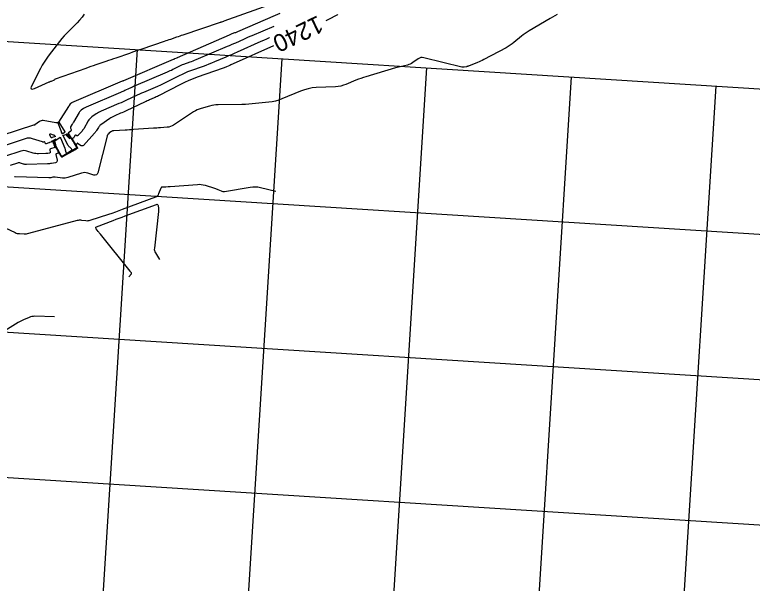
# Model space of a CAD drawing. Extents: x 658976 to 668721, y 639543 to 647196.
# Drawn here: x 662592.9 to 662847.1, y 641855.6 to 642051.6 of the extents above; entities that cross this region are included whole.
import ezdxf

# ---------------------------------------------------------------- set-up
doc = ezdxf.new("R2010")
doc.units = 0
for name, color, linetype in [('Ex_Contour Labels', 7, 'Continuous'), ('Ex_Major Contours', 7, 'Continuous'), ('Ex_Minor Contours', 7, 'Continuous'), ('R_Grid', 7, 'Continuous')]:
    doc.layers.add(name, color=color, linetype=linetype)

msp = doc.modelspace()

# ---------------------------------------------------------------- linework, layer by layer
at = {"layer": 'Ex_Major Contours'}
for points in [[(662704.31, 642051.66), (662704.09, 642051.55), (662703.87, 642051.43), (662703.01, 642050.95), (662702.79, 642050.83), (662702.58, 642050.71), (662702.36, 642050.6), (662702.14, 642050.49), (662700.13, 642049.48)], [(662682.09, 642040.84), (662668.19, 642034.6), (662667.91, 642034.48), (662667.62, 642034.35), (662667.33, 642034.23), (662667.05, 642034.1), (662665.9, 642033.61), (662665.61, 642033.49), (662665.32, 642033.38), (662665.03, 642033.27), (662664.73, 642033.16), (662655.79, 642029.99), (662654.32, 642029.44), (662652.87, 642028.85), (662651.44, 642028.2), (662650.03, 642027.51), (662642.4, 642023.58), (662642.03, 642023.39), (662641.65, 642023.21), (662641.27, 642023.04), (662640.88, 642022.87), (662639.34, 642022.21), (662638.95, 642022.04), (662638.57, 642021.87), (662638.19, 642021.7), (662637.81, 642021.52), (662631.27, 642018.43), (662630.79, 642018.21), (662630.31, 642018), (662629.83, 642017.78), (662629.35, 642017.57), (662627.42, 642016.75), (662626.95, 642016.53), (662626.48, 642016.29), (662626.03, 642016.03), (662625.6, 642015.74), (662622.49, 642013.56), (662622.25, 642013.38), (662622.04, 642013.17), (662621.85, 642012.95), (662621.69, 642012.7), (662621.08, 642011.66), (662620.92, 642011.4), (662620.75, 642011.15), (662620.57, 642010.92), (662620.37, 642010.69), (662616.58, 642006.53), (662616.39, 642006.38), (662616.2, 642006.31), (662615.99, 642006.32), (662615.76, 642006.42), (662614.5, 642007.22), (662614.45, 642007.24), (662614.41, 642007.24), (662614.38, 642007.22), (662614.34, 642007.18), (662614.2, 642006.93), (662614.18, 642006.91), (662614.16, 642006.88), (662614.14, 642006.86), (662614.12, 642006.84), (662614.01, 642006.75), (662614, 642006.74), (662613.98, 642006.73), (662613.97, 642006.73), (662613.96, 642006.72), (662613.91, 642006.7), (662613.9, 642006.69), (662613.89, 642006.69), (662613.89, 642006.68), (662613.9, 642006.67), (662614.49, 642005.69), (662614.53, 642005.6), (662614.53, 642005.52), (662614.49, 642005.46), (662614.42, 642005.4), (662614.05, 642005.18), (662613.96, 642005.13), (662613.87, 642005.07), (662613.77, 642005.02), (662613.68, 642004.97), (662609.29, 642002.53), (662609.18, 642002.48), (662609.08, 642002.49), (662609, 642002.54), (662608.93, 642002.63), (662608.68, 642003.09), (662608.61, 642003.21), (662608.55, 642003.32), (662608.48, 642003.43), (662608.4, 642003.54), (662607.78, 642004.46), (662607.75, 642004.51), (662607.74, 642004.52), (662607.74, 642004.5), (662607.75, 642004.45), (662607.88, 642004.11), (662607.89, 642004.08), (662607.89, 642004.05), (662607.89, 642004.03), (662607.89, 642004), (662607.86, 642003.88), (662607.85, 642003.85), (662607.83, 642003.83), (662607.81, 642003.82), (662607.79, 642003.8), (662607.23, 642003.64), (662607.14, 642003.6), (662607.08, 642003.54), (662607.06, 642003.46), (662607.06, 642003.36), (662607.44, 642001.38), (662607.45, 642001.07), (662607.36, 642000.83), (662607.17, 642000.66), (662606.88, 642000.56), (662605.5, 642000.29), (662605.16, 642000.23), (662604.81, 642000.18), (662604.46, 642000.15), (662604.11, 642000.14), (662596.88, 641999.95), (662596.62, 641999.95), (662596.36, 641999.98), (662596.1, 642000.03), (662595.85, 642000.1), (662594.84, 642000.42), (662594.59, 642000.47), (662594.34, 642000.49), (662594.09, 642000.47), (662593.83, 642000.41), (662591.26, 641999.57)]]:
    msp.add_lwpolyline(points, dxfattribs=at)
at = {"layer": 'Ex_Minor Contours'}
for points in [[(662616.81, 642051.7), (662616.06, 642050.69), (662615.24, 642049.72), (662614.38, 642048.79), (662610.82, 642045.17), (662609.94, 642044.25), (662609.1, 642043.31), (662608.28, 642042.33), (662607.5, 642041.34), (662604.41, 642037.29), (662603.66, 642036.26), (662602.96, 642035.21), (662602.31, 642034.12), (662601.71, 642033), (662598.72, 642027.13), (662598.44, 642026.41), (662598.5, 642026), (662598.9, 642025.92), (662599.64, 642026.16), (662604.74, 642028.39), (662604.93, 642028.47), (662605.11, 642028.55), (662605.3, 642028.63), (662605.48, 642028.71), (662606.52, 642029.16), (662606.56, 642029.18), (662606.59, 642029.2), (662606.62, 642029.22), (662606.64, 642029.25), (662606.74, 642029.36), (662606.77, 642029.38), (662606.79, 642029.4), (662606.83, 642029.42), (662606.86, 642029.44), (662617.46, 642033.17), (662618.33, 642033.47), (662619.19, 642033.77), (662620.06, 642034.07), (662620.92, 642034.37), (662624.39, 642035.55), (662625.26, 642035.84), (662626.12, 642036.14), (662626.99, 642036.44), (662627.85, 642036.74), (662632.49, 642038.36), (662633.55, 642038.73), (662634.61, 642039.1), (662635.67, 642039.46), (662636.74, 642039.83), (662644.48, 642042.44), (662645.02, 642042.63), (662645.55, 642042.81), (662646.09, 642042.99), (662646.62, 642043.18), (662648.76, 642043.92), (662649.3, 642044.11), (662649.84, 642044.29), (662650.37, 642044.47), (662650.91, 642044.65), (662663.82, 642048.99), (662663.94, 642049.02), (662664.05, 642049.06), (662664.17, 642049.1), (662664.29, 642049.14), (662664.95, 642049.37), (662664.96, 642049.38), (662664.98, 642049.38), (662664.99, 642049.39), (662665, 642049.39), (662665.06, 642049.42), (662665.07, 642049.42), (662665.08, 642049.43), (662665.1, 642049.43), (662665.11, 642049.44), (662682.24, 642055.52)], [(662684.22, 642051.97), (662682.6, 642051.24), (662669.63, 642045.65), (662669.4, 642045.55), (662669.16, 642045.45), (662668.92, 642045.36), (662668.68, 642045.27), (662667.7, 642044.92), (662667.46, 642044.84), (662667.22, 642044.74), (662666.98, 642044.65), (662666.75, 642044.54), (662648.88, 642036.7), (662648.86, 642036.69), (662648.85, 642036.68), (662648.83, 642036.68), (662648.82, 642036.67), (662648.75, 642036.65), (662648.74, 642036.64), (662648.72, 642036.64), (662648.71, 642036.63), (662648.69, 642036.63), (662647.96, 642036.3), (662647.83, 642036.24), (662647.71, 642036.18), (662647.58, 642036.13), (662647.45, 642036.07), (662630.38, 642028.81), (662630.35, 642028.79), (662630.31, 642028.77), (662630.27, 642028.76), (662630.24, 642028.74), (662630.09, 642028.67), (662630.05, 642028.65), (662630.01, 642028.64), (662629.98, 642028.62), (662629.94, 642028.6), (662612.43, 642021.13), (662612.39, 642021.11), (662612.34, 642021.09), (662612.3, 642021.07), (662612.26, 642021.04), (662612.1, 642020.93), (662612.07, 642020.9), (662612.03, 642020.87), (662612, 642020.83), (662611.98, 642020.79), (662611.68, 642020.29), (662611.62, 642020.19), (662611.57, 642020.1), (662611.51, 642020), (662611.44, 642019.9), (662608, 642014.58), (662608, 642014.57), (662607.99, 642014.56), (662608, 642014.55), (662608, 642014.55), (662608.01, 642014.52), (662608.02, 642014.51), (662608.02, 642014.5), (662608.02, 642014.5), (662608.03, 642014.49), (662610.14, 642011.17), (662610.15, 642011.15), (662610.15, 642011.12), (662610.14, 642011.1), (662610.13, 642011.08), (662610.03, 642010.99), (662610.01, 642010.97), (662609.99, 642010.95), (662609.96, 642010.93), (662609.94, 642010.9), (662609.41, 642010.45), (662609.41, 642010.44), (662609.41, 642010.44), (662609.4, 642010.45), (662609.4, 642010.45), (662609.39, 642010.48), (662609.38, 642010.48), (662609.03, 642011.11), (662608.98, 642011.22), (662608.93, 642011.33), (662608.88, 642011.44), (662608.84, 642011.55), (662607.88, 642014.22), (662607.85, 642014.28), (662607.8, 642014.33), (662607.74, 642014.35), (662607.67, 642014.36), (662607.35, 642014.33), (662607.27, 642014.33), (662607.2, 642014.33), (662607.12, 642014.34), (662607.04, 642014.35), (662602.63, 642015.04), (662602.3, 642015.06), (662601.98, 642015.01), (662601.68, 642014.91), (662601.39, 642014.74), (662599.77, 642013.55), (662599.74, 642013.53), (662599.72, 642013.52), (662599.69, 642013.51), (662599.66, 642013.51), (662599.51, 642013.49), (662599.5, 642013.49), (662599.48, 642013.49), (662599.47, 642013.49), (662599.46, 642013.5), (662599.41, 642013.51), (662599.39, 642013.52), (662599.38, 642013.52), (662599.37, 642013.51), (662599.36, 642013.51), (662582.63, 642008.05)], [(662779.93, 642051.64), (662779.12, 642051.17), (662778.31, 642050.7), (662777.5, 642050.23), (662770.24, 642046.01), (662769.54, 642045.58), (662768.85, 642045.12), (662768.18, 642044.64), (662767.53, 642044.13), (662764.98, 642042.02), (662764.33, 642041.51), (662763.66, 642041.04), (662762.97, 642040.6), (662762.25, 642040.19), (662754.58, 642036.1), (662754.03, 642035.82), (662753.48, 642035.55), (662752.93, 642035.3), (662752.36, 642035.07), (662749.32, 642033.85), (662749.13, 642033.79), (662748.95, 642033.73), (662748.76, 642033.68), (662748.57, 642033.64), (662747.8, 642033.51), (662747.61, 642033.48), (662747.42, 642033.48), (662747.22, 642033.5), (662747.03, 642033.53), (662733.86, 642036.73), (662733.34, 642036.8), (662732.85, 642036.77), (662732.38, 642036.62), (662731.93, 642036.36), (662730.15, 642035.08), (662729.71, 642034.79), (662729.25, 642034.55), (662728.77, 642034.36), (662728.26, 642034.22), (662726.2, 642033.75), (662725.69, 642033.63), (662725.18, 642033.5), (662724.67, 642033.36), (662724.16, 642033.22), (662713.96, 642030.19), (662713.07, 642029.91), (662712.2, 642029.61), (662711.33, 642029.29), (662710.47, 642028.95), (662707.04, 642027.53), (662706.18, 642027.22), (662705.29, 642026.98), (662704.39, 642026.82), (662703.48, 642026.74), (662696.84, 642026.44), (662695.44, 642026.32), (662694.06, 642026.07), (662692.71, 642025.71), (662691.39, 642025.22), (662684.94, 642022.54), (662683.86, 642022.13), (662682.75, 642021.8), (662681.63, 642021.56), (662680.48, 642021.39), (662675.85, 642020.9), (662674.69, 642020.79), (662673.53, 642020.71), (662672.37, 642020.65), (662671.21, 642020.62), (662662.97, 642020.49), (662662.23, 642020.46), (662661.5, 642020.38), (662660.77, 642020.25), (662660.05, 642020.07), (662657.19, 642019.28), (662656.48, 642019.06), (662655.8, 642018.78), (662655.15, 642018.45), (662654.52, 642018.07), (662647.6, 642013.5), (662647.1, 642013.21), (662646.56, 642012.99), (662646.01, 642012.84), (662645.43, 642012.76), (662643.07, 642012.59), (662642.47, 642012.54), (662641.88, 642012.5), (662641.29, 642012.46), (662640.7, 642012.42), (662633.82, 642011.95), (662633.1, 642011.9), (662632.38, 642011.86), (662631.65, 642011.82), (662630.93, 642011.78), (662626.98, 642011.57), (662626.79, 642011.55), (662626.61, 642011.5), (662626.43, 642011.43), (662626.27, 642011.33), (662625.34, 642010.68), (662625.33, 642010.67), (662625.32, 642010.66), (662625.31, 642010.65), (662625.31, 642010.64), (662625.28, 642010.59), (662625.27, 642010.58), (662625.26, 642010.57), (662625.25, 642010.56), (662625.25, 642010.55), (662624.96, 642010.24), (662624.93, 642010.2), (662624.9, 642010.16), (662624.87, 642010.11), (662624.85, 642010.06), (662624.78, 642009.87), (662624.76, 642009.82), (662624.74, 642009.77), (662624.73, 642009.72), (662624.71, 642009.67), (662621.48, 641997.04), (662621.29, 641996.59), (662621.01, 641996.32), (662620.63, 641996.22), (662620.15, 641996.3), (662618.03, 641996.97), (662617.5, 641997.09), (662616.97, 641997.13), (662616.44, 641997.09), (662615.91, 641996.96), (662611.17, 641995.43), (662610.71, 641995.31), (662610.24, 641995.24), (662609.76, 641995.22), (662609.28, 641995.26), (662606.76, 641995.61), (662606.57, 641995.62), (662606.39, 641995.62), (662606.21, 641995.6), (662606.03, 641995.56), (662605.3, 641995.37), (662605.12, 641995.32), (662604.94, 641995.3), (662604.75, 641995.28), (662604.57, 641995.28), (662593.02, 641995.69), (662592.89, 641995.7), (662592.76, 641995.72)], [(662682.19, 642047.54), (662674.57, 642044.3), (662673.86, 642044), (662673.15, 642043.7), (662672.45, 642043.38), (662671.74, 642043.07), (662668.93, 642041.81), (662668.23, 642041.5), (662667.52, 642041.19), (662666.82, 642040.88), (662666.11, 642040.58), (662655.26, 642035.96), (662654.75, 642035.75), (662654.24, 642035.54), (662653.73, 642035.35), (662653.21, 642035.16), (662651.08, 642034.41), (662650.59, 642034.23), (662650.11, 642034.03), (662649.64, 642033.81), (662649.17, 642033.58), (662647.32, 642032.63), (662646.85, 642032.39), (662646.38, 642032.17), (662645.91, 642031.95), (662645.43, 642031.74), (662633.81, 642026.8), (662633.44, 642026.63), (662633.07, 642026.47), (662632.69, 642026.3), (662632.33, 642026.13), (662630.85, 642025.43), (662630.48, 642025.26), (662630.11, 642025.09), (662629.74, 642024.93), (662629.37, 642024.77), (662617.52, 642019.71), (662617.29, 642019.61), (662617.06, 642019.49), (662616.84, 642019.36), (662616.62, 642019.21), (662615.77, 642018.62), (662615.57, 642018.46), (662615.39, 642018.28), (662615.23, 642018.09), (662615.09, 642017.88), (662613.11, 642014.5), (662613, 642014.32), (662612.89, 642014.14), (662612.78, 642013.96), (662612.67, 642013.78), (662612.11, 642012.91), (662612.06, 642012.81), (662612.03, 642012.71), (662612.04, 642012.6), (662612.08, 642012.49), (662612.34, 642011.97), (662612.37, 642011.91), (662612.38, 642011.84), (662612.36, 642011.78), (662612.34, 642011.72), (662612.19, 642011.47), (662612.15, 642011.41), (662612.1, 642011.35), (662612.06, 642011.3), (662612, 642011.25), (662611.33, 642010.7), (662611.32, 642010.69), (662611.32, 642010.69), (662611.32, 642010.69), (662613.93, 642006.39), (662614.09, 642006.02), (662614.09, 642005.69), (662613.93, 642005.4), (662613.62, 642005.14), (662611.78, 642004.07), (662611.51, 642003.91), (662611.25, 642003.76), (662610.98, 642003.6), (662610.71, 642003.45), (662609.63, 642002.85), (662609.37, 642002.75), (662609.15, 642002.76), (662608.95, 642002.87), (662608.79, 642003.09), (662607.87, 642004.76), (662607.69, 642005.09), (662607.5, 642005.4), (662607.3, 642005.72), (662607.1, 642006.03), (662606.09, 642007.53), (662606.01, 642007.7), (662606, 642007.84), (662606.06, 642007.98), (662606.2, 642008.1), (662606.87, 642008.56), (662607, 642008.64), (662607.04, 642008.68), (662606.99, 642008.66), (662606.85, 642008.59), (662605.49, 642007.86), (662605.47, 642007.85), (662605.46, 642007.83), (662605.46, 642007.82), (662605.46, 642007.8), (662605.51, 642007.68), (662605.51, 642007.68), (662605.51, 642007.68), (662605.5, 642007.67), (662604.95, 642007.51), (662604.85, 642007.48), (662604.76, 642007.45), (662604.67, 642007.41), (662604.58, 642007.38), (662603.75, 642007.04), (662603.66, 642007.01), (662603.58, 642007.03), (662603.52, 642007.07), (662603.47, 642007.15), (662603.27, 642007.58), (662603.23, 642007.64), (662603.18, 642007.68), (662603.12, 642007.7), (662603.05, 642007.7), (662602.76, 642007.67), (662602.69, 642007.66), (662602.61, 642007.67), (662602.54, 642007.68), (662602.47, 642007.7), (662598.93, 642008.82), (662598.31, 642008.96), (662597.7, 642009.01), (662597.09, 642008.96), (662596.48, 642008.81), (662585.95, 642005.37)], [(662680.75, 642043.65), (662680.61, 642043.59), (662679.62, 642043.16), (662678.64, 642042.72), (662677.65, 642042.28), (662669.5, 642038.63), (662668.54, 642038.2), (662667.57, 642037.77), (662666.6, 642037.35), (662665.63, 642036.93), (662661.73, 642035.28), (662660.75, 642034.87), (662659.77, 642034.48), (662658.78, 642034.1), (662657.79, 642033.74), (662653.43, 642032.2), (662652.45, 642031.83), (662651.49, 642031.44), (662650.54, 642031.01), (662649.6, 642030.55), (662645.88, 642028.63), (662644.95, 642028.16), (662644.01, 642027.71), (662643.06, 642027.27), (662642.1, 642026.85), (662637.24, 642024.79), (662636.53, 642024.48), (662635.82, 642024.17), (662635.12, 642023.85), (662634.42, 642023.52), (662631.62, 642022.2), (662630.92, 642021.87), (662630.21, 642021.55), (662629.5, 642021.24), (662628.79, 642020.93), (662622.61, 642018.29), (662622.19, 642018.1), (662621.77, 642017.88), (662621.37, 642017.64), (662620.98, 642017.39), (662619.44, 642016.31), (662619.08, 642016.02), (662618.75, 642015.7), (662618.45, 642015.35), (662618.2, 642014.96), (662616.63, 642012.27), (662616.45, 642011.99), (662616.26, 642011.72), (662616.06, 642011.46), (662615.84, 642011.2), (662614.63, 642009.88), (662614.56, 642009.82), (662614.48, 642009.79), (662614.4, 642009.8), (662614.31, 642009.84), (662613.95, 642010.06), (662613.86, 642010.1), (662613.79, 642010.1), (662613.72, 642010.06), (662613.66, 642009.99), (662613.22, 642009.25), (662613.18, 642009.18), (662613.13, 642009.12), (662613.08, 642009.06), (662613.02, 642009.01), (662612.67, 642008.72), (662612.66, 642008.72), (662612.65, 642008.71), (662612.65, 642008.71), (662612.64, 642008.71), (662612.61, 642008.7), (662612.61, 642008.69), (662612.61, 642008.69), (662612.61, 642008.68), (662612.61, 642008.68), (662614.21, 642006.04), (662614.31, 642005.81), (662614.31, 642005.61), (662614.21, 642005.43), (662614.02, 642005.27), (662613.04, 642004.7), (662612.8, 642004.56), (662612.56, 642004.42), (662612.31, 642004.28), (662612.06, 642004.14), (662609.54, 642002.74), (662609.32, 642002.65), (662609.13, 642002.66), (662608.96, 642002.76), (662608.81, 642002.95), (662608.29, 642003.89), (662608.16, 642004.13), (662608.02, 642004.36), (662607.88, 642004.59), (662607.73, 642004.82), (662606.46, 642006.7), (662606.4, 642006.79), (662606.37, 642006.82), (662606.37, 642006.78), (662606.4, 642006.67), (662606.69, 642005.9), (662606.7, 642005.88), (662606.7, 642005.87), (662606.7, 642005.85), (662606.7, 642005.84), (662606.68, 642005.78), (662606.68, 642005.76), (662606.67, 642005.75), (662606.66, 642005.74), (662606.64, 642005.74), (662605.23, 642005.32), (662605.09, 642005.25), (662605.01, 642005.16), (662604.97, 642005.05), (662604.97, 642004.9), (662605.1, 642004.24), (662605.1, 642004.1), (662605.07, 642003.99), (662604.98, 642003.91), (662604.85, 642003.87), (662604.23, 642003.75), (662604.08, 642003.72), (662603.92, 642003.7), (662603.77, 642003.69), (662603.61, 642003.68), (662601.08, 642003.61), (662600.61, 642003.62), (662600.14, 642003.67), (662599.68, 642003.75), (662599.22, 642003.88), (662597.05, 642004.56), (662596.53, 642004.69), (662596.02, 642004.72), (662595.51, 642004.68), (662594.99, 642004.56), (662589.28, 642002.69)], [(662589.52, 641978.15), (662593.02, 641976.47), (662593.38, 641976.31), (662593.75, 641976.2), (662594.14, 641976.13), (662594.53, 641976.09), (662596.12, 641976.04), (662596.52, 641976.04), (662596.91, 641976.07), (662597.3, 641976.13), (662597.69, 641976.22), (662614.45, 641980.7), (662614.82, 641980.78), (662615.18, 641980.82), (662615.55, 641980.83), (662615.92, 641980.79), (662617.41, 641980.59), (662617.78, 641980.56), (662618.15, 641980.57), (662618.51, 641980.63), (662618.87, 641980.72), (662625.3, 641982.82), (662626.49, 641983.21), (662627.67, 641983.62), (662628.85, 641984.04), (662630.02, 641984.48), (662641.49, 641988.81), (662641.85, 641988.99), (662642.15, 641989.23), (662642.39, 641989.52), (662642.57, 641989.88), (662643.36, 641991.93), (662643.43, 641992.05), (662643.51, 641992.13), (662643.62, 641992.19), (662643.76, 641992.21), (662644.34, 641992.24), (662644.49, 641992.25), (662644.63, 641992.26), (662644.78, 641992.27), (662644.92, 641992.28), (662645.7, 641992.33), (662645.88, 641992.34), (662646.05, 641992.35), (662646.23, 641992.37), (662646.41, 641992.38), (662655.87, 641993.08), (662656.53, 641993.1), (662657.19, 641993.05), (662657.84, 641992.95), (662658.48, 641992.78), (662661.72, 641991.78), (662662.02, 641991.68), (662662.31, 641991.57), (662662.6, 641991.46), (662662.89, 641991.33), (662664.03, 641990.82), (662664.31, 641990.71), (662664.61, 641990.65), (662664.91, 641990.64), (662665.21, 641990.67), (662674, 641992.16), (662674.9, 641992.27), (662675.8, 641992.28), (662676.7, 641992.21), (662677.59, 641992.04), (662682.92, 641990.76)], [(662632.25, 641961.24), (662633.08, 641962.29), (662633.13, 641962.37), (662633.14, 641962.44), (662633.12, 641962.51), (662633.08, 641962.58), (662632.83, 641962.86), (662632.77, 641962.94), (662632.71, 641963.01), (662632.65, 641963.08), (662632.6, 641963.15), (662622.39, 641975.87), (662622.2, 641976.11), (662622.02, 641976.34), (662621.83, 641976.58), (662621.64, 641976.81), (662620.9, 641977.75), (662620.77, 641977.97), (662620.76, 641978.16), (662620.86, 641978.32), (662621.09, 641978.44), (662626.78, 641980.63), (662627.82, 641981.03), (662628.87, 641981.43), (662629.92, 641981.82), (662630.96, 641982.2), (662641.74, 641986.16), (662641.96, 641986.21), (662642.12, 641986.17), (662642.24, 641986.04), (662642.3, 641985.83), (662642.44, 641984.8), (662642.47, 641984.54), (662642.48, 641984.28), (662642.47, 641984.02), (662642.45, 641983.77), (662640.99, 641971.09), (662640.97, 641970.65), (662641.03, 641970.23), (662641.16, 641969.83), (662641.36, 641969.44), (662642.77, 641967.17)], [(662606.55, 641947.4), (662599.83, 641947.59), (662599.31, 641947.57), (662598.8, 641947.51), (662598.31, 641947.39), (662597.82, 641947.21), (662595.89, 641946.41), (662595.41, 641946.2), (662594.94, 641945.97), (662594.49, 641945.72), (662594.04, 641945.46), (662581.37, 641937.67)]]:
    msp.add_lwpolyline(points, dxfattribs=at)
for points in [[(662606.26, 642010.16), (662606.34, 642010.12), (662606.42, 642010.06), (662606.49, 642010), (662606.89, 642009.58), (662606.89, 642009.58), (662606.89, 642009.58), (662606.89, 642009.57), (662606.89, 642009.57), (662606.9, 642009.56), (662606.9, 642009.55), (662606.9, 642009.55), (662606.9, 642009.55), (662606.89, 642009.55), (662605.78, 642009.21), (662605.75, 642009.2), (662605.72, 642009.19), (662605.69, 642009.17), (662605.66, 642009.16), (662605.55, 642009.11), (662605.52, 642009.11), (662605.49, 642009.11), (662605.47, 642009.12), (662605.46, 642009.15), (662604.97, 642010.19), (662604.92, 642010.34), (662604.94, 642010.43), (662605.03, 642010.47), (662605.19, 642010.45), (662606.16, 642010.19)], [(662608.57, 642009.25), (662608.71, 642008.92), (662609.99, 642005.84), (662610.08, 642005.64), (662610.15, 642005.44), (662610.22, 642005.23), (662610.28, 642005.02), (662610.51, 642004.18), (662610.58, 642004.01), (662610.69, 642003.92), (662610.83, 642003.91), (662611, 642003.98), (662612.37, 642004.79), (662612.51, 642004.9), (662612.56, 642005.02), (662612.53, 642005.15), (662612.42, 642005.29), (662611.81, 642005.86), (662611.66, 642006), (662611.52, 642006.16), (662611.4, 642006.33), (662611.3, 642006.51), (662609.5, 642009.79), (662609.48, 642009.84), (662609.49, 642009.88), (662609.51, 642009.92), (662609.55, 642009.94), (662610.65, 642010.44), (662610.84, 642010.5), (662611.02, 642010.49), (662611.17, 642010.41), (662611.31, 642010.27), (662612.49, 642008.57), (662612.68, 642008.29), (662612.87, 642008), (662613.06, 642007.72), (662613.24, 642007.42), (662613.95, 642006.25), (662614.07, 642005.97), (662614.07, 642005.72), (662613.95, 642005.5), (662613.72, 642005.31), (662610.14, 642003.21), (662610.04, 642003.15), (662609.94, 642003.09), (662609.83, 642003.03), (662609.73, 642002.98), (662609.31, 642002.74), (662609.21, 642002.71), (662609.12, 642002.71), (662609.05, 642002.75), (662608.98, 642002.84), (662607.18, 642006.12), (662607.09, 642006.29), (662606.99, 642006.45), (662606.89, 642006.62), (662606.78, 642006.78), (662606.35, 642007.42), (662606.27, 642007.58), (662606.26, 642007.72), (662606.32, 642007.85), (662606.45, 642007.96), (662608.43, 642009.29), (662608.47, 642009.31), (662608.51, 642009.32), (662608.55, 642009.29)], [(662610.94, 642009.76), (662610.75, 642010.1), (662610.73, 642010.14), (662610.73, 642010.15), (662610.73, 642010.16), (662610.73, 642010.16), (662610.74, 642010.16), (662610.89, 642010.23), (662610.91, 642010.24), (662610.94, 642010.24), (662610.96, 642010.23), (662610.98, 642010.21), (662611.84, 642008.97), (662611.91, 642008.86), (662611.92, 642008.82), (662611.88, 642008.84), (662611.78, 642008.92), (662611.1, 642009.55), (662611.05, 642009.6), (662611.01, 642009.65), (662610.97, 642009.7)], [(662606.62, 642007.75), (662606.63, 642007.72), (662606.73, 642007.49), (662606.74, 642007.45), (662606.76, 642007.41), (662606.77, 642007.37), (662606.78, 642007.33), (662606.93, 642006.78), (662606.95, 642006.7), (662606.95, 642006.67), (662606.93, 642006.69), (662606.88, 642006.76), (662606.49, 642007.47), (662606.49, 642007.49), (662606.48, 642007.5), (662606.47, 642007.52), (662606.46, 642007.53), (662606.42, 642007.59), (662606.41, 642007.6), (662606.41, 642007.61), (662606.42, 642007.63), (662606.43, 642007.64), (662606.6, 642007.75), (662606.61, 642007.76), (662606.61, 642007.76), (662606.61, 642007.75)]]:
    msp.add_lwpolyline(points, close=True, dxfattribs=at)
at = {"layer": 'R_Grid'}
for p, q in [((661637.1, 642102.2), (663134.15, 642008.18)), ((661633.97, 642052.3), (663131.02, 641958.27)), ((662619.46, 641790.01), (662635.13, 642039.52)), ((662669.37, 641786.87), (662685.04, 642036.38)), ((662719.27, 641783.74), (662734.94, 642033.25)), ((662769.17, 641780.61), (662784.84, 642030.11)), ((662819.07, 641777.47), (662834.74, 642026.98)), ((661630.83, 642002.39), (663127.88, 641908.37)), ((661627.7, 641952.49), (663124.75, 641858.47))]:
    msp.add_line(p, q, dxfattribs=at)

# ---------------------------------------------------------------- texts
at = {"layer": 'Ex_Contour Labels'}
msp.add_text('1240', height=6, rotation=205.6062, dxfattribs=at).set_placement((662697.33, 642051.47))

doc.saveas('drawing.dxf')
